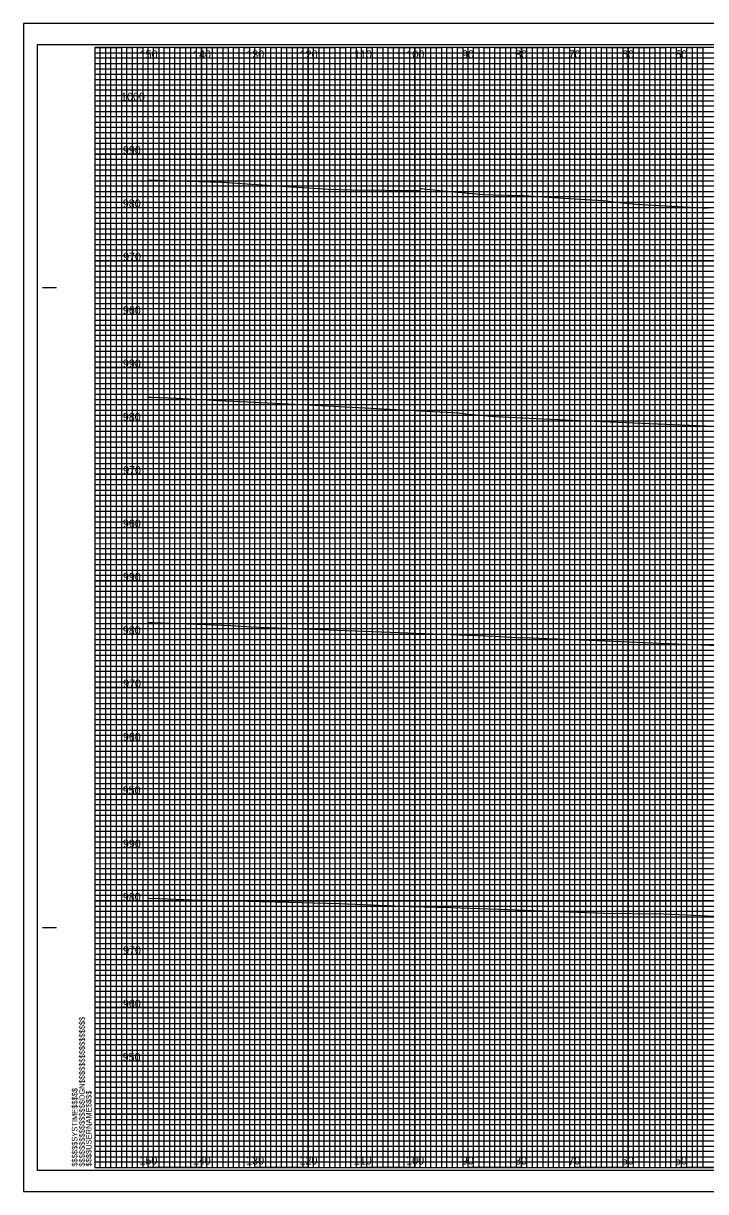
# Model space of a CAD drawing. Extents: x -13 to 760, y -5 to 1491.
# Drawn here: x 423.3 to 551.2, y 314.5 to 533.5 of the extents above; entities that cross this region are included whole.
import ezdxf

# ---------------------------------------------------------------- set-up
doc = ezdxf.new("R2010")
doc.units = 0
for name, color, linetype in [('Default', 7, 'Continuous'), ('Exist XS Ground Line', 7, 'Continuous'), ('Prop XS Elevation Labels', 7, 'Continuous'), ('Prop XS Offset Labels', 7, 'Continuous'), ('Sheet Cross Section CELL', 7, 'Continuous'), ('Sheet Cross Section Grid Major CELL', 7, 'Continuous'), ('Sheet Cross Section Grid Middle CELL', 7, 'Continuous'), ('Sheet Cross Section Grid Minor 1 CELL', 7, 'Continuous'), ('Sheet Cross Section Grid Minor 2 CELL', 7, 'Continuous'), ('Sheet Cutting Line CELL', 7, 'Continuous'), ('Sheet DOT Grid CELL', 7, 'Continuous'), ('Sheet Plot Border Inside CELL', 7, 'Continuous'), ('Sheet Plot Border Outside CELL', 7, 'Continuous')]:
    doc.layers.add(name, color=color, linetype=linetype)

msp = doc.modelspace()

# ---------------------------------------------------------------- linework, layer by layer
at = {"layer": 'Exist XS Ground Line'}
for points in [[(446.7, 504.16), (451.89, 503.99), (460.45, 503.71), (480.47, 502.43), (484.82, 502.27), (497.61, 502.17), (497.66, 502.17), (497.71, 502.17), (497.79, 502.5), (497.89, 502.52), (501.29, 502.2), (509.54, 501.41), (511.38, 501.37), (517.12, 501.21), (518.1, 501.15), (525.54, 500.68), (532.07, 500.32), (533.9, 500.06), (538.06, 499.6), (551.67, 498.85)], [(446.7, 504.16), (451.89, 503.99), (460.45, 503.71), (480.47, 502.43), (484.82, 502.27), (497.61, 502.17), (497.66, 502.17), (497.71, 502.17), (497.79, 502.5), (497.89, 502.52), (501.29, 502.2), (509.54, 501.41), (511.38, 501.37), (517.12, 501.21), (518.1, 501.15), (525.54, 500.68), (532.07, 500.32), (533.9, 500.06), (538.06, 499.6), (551.67, 498.85)], [(446.7, 463.45), (447.34, 463.43), (451.94, 463.25), (459.82, 462.83), (462.69, 462.7), (476.73, 462.02), (504.86, 460.48), (506.67, 460.24), (511.85, 459.84), (519.4, 459.42), (530.33, 458.91), (537.74, 458.61), (548.17, 458.18), (555.59, 457.89)], [(446.7, 463.45), (447.34, 463.43), (451.94, 463.25), (459.82, 462.83), (462.69, 462.7), (476.73, 462.02), (504.86, 460.48), (506.67, 460.24), (511.85, 459.84), (519.4, 459.42), (530.33, 458.91), (537.74, 458.61), (548.17, 458.18), (555.59, 457.89)], [(446.7, 421.25), (447.6, 421.19), (462.2, 420.6), (466.03, 420.41), (511.53, 418.63), (515.75, 418.41), (518.64, 418.29), (521.8, 418.19), (563.87, 416.45)], [(446.7, 421.25), (447.6, 421.19), (462.2, 420.6), (466.03, 420.41), (511.53, 418.63), (515.75, 418.41), (518.64, 418.29), (521.8, 418.19), (563.87, 416.45)], [(446.7, 369.54), (448.61, 369.45), (451.9, 369.31), (451.9, 369.31), (454.92, 369.22), (473.04, 368.78), (480.19, 368.56), (482.5, 368.49), (495.86, 367.98), (503.4, 367.74), (510.75, 367.51), (532.16, 366.7), (543.34, 366.61), (564.26, 365.65)], [(446.7, 369.54), (448.61, 369.45), (451.9, 369.31), (451.9, 369.31), (454.92, 369.22), (473.04, 368.78), (480.19, 368.56), (482.5, 368.49), (495.86, 367.98), (503.4, 367.74), (510.75, 367.51), (532.16, 366.7), (543.34, 366.61), (564.26, 365.65)]]:
    msp.add_lwpolyline(points, dxfattribs=at)
at = {"layer": 'Sheet Cross Section CELL'}
for p, q in [((426.9, 484), (429.4, 484)), ((427, 484), (429.5, 484)), ((426.9, 364), (429.4, 364)), ((427, 364), (429.5, 364)), ((436.7, 319), (436.7, 319)), ((436.7, 319), (436.7, 319)), ((436.7, 319), (436.7, 319)), ((436.7, 319), (436.7, 319)), ((436.7, 319), (436.7, 319)), ((436.7, 319), (436.7, 319)), ((436.7, 319), (436.7, 319))]:
    msp.add_line(p, q, dxfattribs=at)
msp.add_lwpolyline([(756.7, 529), (436.7, 529), (436.7, 319), (756.7, 319)], close=True, dxfattribs=at)
at = {"layer": 'Sheet Cross Section Grid Major CELL'}
for p, q in [((446.7, 529), (436.7, 529)), ((446.7, 319), (446.7, 529)), ((466.7, 529), (456.7, 529)), ((456.7, 529), (456.7, 319)), ((466.7, 319), (466.7, 529)), ((486.7, 529), (476.7, 529)), ((476.7, 529), (476.7, 319)), ((486.7, 319), (486.7, 529)), ((506.7, 529), (496.7, 529)), ((496.7, 529), (496.7, 319)), ((506.7, 319), (506.7, 529)), ((526.7, 529), (516.7, 529)), ((516.7, 529), (516.7, 319)), ((526.7, 319), (526.7, 529)), ((546.7, 529), (536.7, 529)), ((536.7, 529), (536.7, 319)), ((546.7, 319), (546.7, 529)), ((456.7, 319), (446.7, 319)), ((476.7, 319), (466.7, 319)), ((496.7, 319), (486.7, 319)), ((516.7, 319), (506.7, 319)), ((536.7, 319), (526.7, 319)), ((556.7, 319), (546.7, 319))]:
    msp.add_line(p, q, dxfattribs=at)
for points in [[(436.7, 519), (756.7, 519), (756.7, 509), (436.7, 509)], [(436.7, 499), (756.7, 499), (756.7, 489), (436.7, 489)], [(436.7, 479), (756.7, 479), (756.7, 469), (436.7, 469)], [(436.7, 459), (756.7, 459), (756.7, 449), (436.7, 449)], [(436.7, 439), (756.7, 439), (756.7, 429), (436.7, 429)], [(436.7, 419), (756.7, 419), (756.7, 409), (436.7, 409)], [(436.7, 399), (756.7, 399), (756.7, 389), (436.7, 389)], [(436.7, 379), (756.7, 379), (756.7, 369), (436.7, 369)], [(436.7, 359), (756.7, 359), (756.7, 349), (436.7, 349)], [(436.7, 339), (756.7, 339), (756.7, 329), (436.7, 329)]]:
    msp.add_lwpolyline(points, dxfattribs=at)
at = {"layer": 'Sheet Cross Section Grid Middle CELL'}
for points in [[(436.7, 529), (441.7, 529), (441.7, 319), (451.7, 319), (451.7, 529), (461.7, 529), (461.7, 319), (471.7, 319), (471.7, 529), (481.7, 529), (481.7, 319), (491.7, 319), (491.7, 529), (501.7, 529), (501.7, 319), (511.7, 319), (511.7, 529), (521.7, 529), (521.7, 319), (531.7, 319), (531.7, 529), (541.7, 529), (541.7, 319), (551.7, 319)], [(436.7, 524), (711.7, 524)], [(436.7, 504), (756.7, 504), (756.7, 514), (436.7, 514)], [(436.7, 484), (756.7, 484), (756.7, 494), (436.7, 494)], [(436.7, 464), (756.7, 464), (756.7, 474), (436.7, 474)], [(436.7, 444), (756.7, 444), (756.7, 454), (436.7, 454)], [(436.7, 424), (756.7, 424), (756.7, 434), (436.7, 434)], [(436.7, 404), (756.7, 404), (756.7, 414), (436.7, 414)], [(436.7, 384), (756.7, 384), (756.7, 394), (436.7, 394)], [(436.7, 364), (756.7, 364), (756.7, 374), (436.7, 374)], [(436.7, 344), (756.7, 344), (756.7, 354), (436.7, 354)], [(436.7, 324), (756.7, 324), (756.7, 334), (436.7, 334)]]:
    msp.add_lwpolyline(points, dxfattribs=at)
at = {"layer": 'Sheet Cross Section Grid Minor 1 CELL'}
for p, q in [((436.7, 528), (696.7, 528)), ((696.7, 526.98), (436.7, 526.98)), ((436.7, 526.98), (436.7, 526)), ((436.7, 526), (696.7, 526)), ((696.7, 524.89), (436.7, 524.89)), ((436.7, 524.89), (436.7, 523)), ((436.7, 523), (756.7, 523))]:
    msp.add_line(p, q, dxfattribs=at)
for points in [[(436.7, 522), (706.7, 522), (756.7, 522), (756.7, 521), (436.7, 521)], [(436.7, 520), (756.7, 520), (756.7, 518), (436.7, 518)], [(436.7, 517), (756.7, 517), (756.7, 516), (436.7, 515.98)], [(436.7, 515), (756.7, 515), (756.7, 513), (436.7, 513)], [(436.7, 512), (756.7, 512), (756.7, 511), (436.7, 511)], [(436.7, 510), (756.7, 510), (756.7, 508), (436.7, 508)], [(436.7, 507), (756.7, 507), (756.7, 506), (436.7, 506)], [(436.7, 505), (756.7, 505), (756.7, 503), (436.7, 503)], [(436.7, 502), (756.7, 502), (756.7, 501), (436.7, 501)], [(436.7, 500), (756.7, 500), (756.7, 498), (436.7, 498)], [(436.7, 497), (756.7, 497), (756.7, 496), (436.7, 496)], [(436.7, 495), (756.7, 495), (756.7, 492.95), (756.7, 492), (756.7, 491), (436.7, 491)], [(436.7, 493), (756.7, 493), (756.7, 492), (436.7, 492)], [(436.7, 490), (756.7, 490), (756.7, 488), (436.7, 488.03)], [(436.7, 488.03), (756.7, 488), (756.7, 487), (436.7, 487)], [(436.7, 486), (756.7, 486), (756.7, 485), (436.7, 485)], [(436.7, 483), (756.7, 483), (756.7, 482), (436.7, 482)], [(436.7, 481), (756.7, 481), (756.7, 480), (436.7, 480)], [(436.63, 477.89), (756.7, 477.89), (756.7, 476.88), (436.63, 476.88)], [(436.7, 476), (756.7, 476), (756.7, 475), (436.7, 475)], [(436.7, 473), (756.7, 473), (756.7, 472), (436.7, 472)], [(436.7, 471), (756.7, 471), (756.7, 470), (436.7, 470)], [(436.7, 468), (756.7, 468), (756.7, 467), (436.7, 467)], [(436.7, 466), (756.7, 466), (756.7, 465), (436.7, 465)], [(436.7, 463), (756.7, 463), (756.7, 462), (436.7, 462)], [(436.7, 461), (756.7, 461), (756.7, 460), (436.7, 460)], [(436.7, 458), (756.7, 458), (756.69, 456.98), (436.7, 457)], [(436.7, 456), (756.7, 456), (756.7, 455), (436.7, 455)], [(436.7, 453), (756.7, 453), (756.7, 452), (436.7, 452)], [(436.7, 451), (756.7, 451), (756.7, 450), (436.7, 450)], [(436.7, 448), (756.7, 448), (756.7, 447), (436.7, 447)], [(436.7, 446), (756.7, 446), (756.7, 445), (436.7, 445)], [(436.7, 443), (756.7, 443), (756.7, 442), (436.7, 442)], [(436.7, 441), (756.7, 441), (756.7, 440), (436.7, 440)], [(436.7, 438), (756.7, 438), (756.7, 437), (436.7, 437)], [(436.7, 435.99), (756.77, 435.91), (756.7, 435), (436.7, 435)], [(436.7, 433), (756.7, 433), (756.7, 432), (436.7, 432)], [(436.7, 431), (756.7, 431), (756.7, 430), (436.7, 430)], [(436.7, 428), (756.7, 428), (756.7, 427), (436.7, 427)], [(436.7, 426), (756.7, 426), (756.7, 425), (436.7, 425)], [(436.7, 423), (756.7, 423), (756.7, 422), (436.7, 422)], [(436.7, 421), (756.7, 421), (756.7, 420), (436.7, 420)], [(436.7, 418), (756.7, 418), (756.7, 417), (436.7, 417)], [(436.7, 416), (756.7, 416), (756.7, 415), (436.7, 415)], [(436.7, 413), (756.7, 413), (756.7, 412), (436.7, 412)], [(436.7, 411), (756.7, 411), (756.7, 410), (436.7, 410)], [(436.7, 408), (756.7, 408), (756.7, 407), (436.7, 407)], [(436.7, 406), (756.7, 406), (756.7, 405), (436.7, 405)], [(436.7, 403), (756.7, 403), (756.7, 402), (436.7, 402)], [(436.7, 401), (756.7, 401), (756.7, 400), (436.7, 400)], [(436.7, 398), (756.7, 398), (756.69, 396.98), (436.7, 397)], [(436.7, 396), (756.7, 396), (756.7, 395), (436.7, 395)], [(436.7, 393), (756.7, 393), (756.7, 392), (436.7, 392)], [(436.7, 391), (756.7, 391), (756.7, 390), (436.7, 390)], [(436.7, 388), (756.7, 388), (756.7, 387), (436.7, 387)], [(436.7, 386), (756.7, 386), (756.7, 385), (436.7, 385)], [(436.7, 383), (756.7, 383), (756.7, 382), (436.7, 382)], [(436.7, 381), (756.7, 381), (756.7, 380), (436.7, 380)], [(436.7, 378), (756.7, 378), (756.7, 377), (436.7, 377)], [(436.7, 375.99), (756.77, 375.91), (756.7, 375), (436.7, 375)], [(436.7, 373), (756.7, 373), (756.7, 372), (436.7, 372)], [(436.7, 371), (756.7, 371), (756.7, 370), (436.7, 370)], [(436.7, 368), (756.7, 368), (756.7, 367), (436.7, 367)], [(436.7, 366), (756.7, 366), (756.7, 365), (436.7, 365)], [(436.7, 363), (756.7, 363), (756.7, 362), (436.7, 362)], [(436.7, 361), (756.7, 361), (756.7, 360), (436.7, 360)], [(436.7, 358), (756.7, 358), (756.7, 357), (436.7, 357)], [(436.7, 356), (756.7, 356), (756.7, 355), (436.7, 355)], [(436.7, 353), (756.7, 353), (756.7, 352), (436.7, 352)], [(436.7, 351), (756.7, 351), (756.7, 350), (436.7, 350)], [(436.7, 348), (756.7, 348), (756.7, 347), (436.7, 347)], [(436.7, 346), (756.7, 346), (756.7, 345), (436.7, 345)], [(436.7, 343), (756.7, 343), (756.7, 342), (436.7, 342)], [(436.7, 341), (756.7, 341), (756.7, 340), (436.7, 340)], [(436.7, 338), (756.7, 338), (756.7, 337), (436.7, 337)], [(436.7, 336), (756.7, 336), (756.7, 335), (436.7, 335)], [(436.7, 333), (756.7, 333), (756.7, 332), (436.7, 332)], [(436.7, 331), (756.7, 331), (756.7, 330), (436.7, 330)], [(436.7, 328), (756.7, 328), (756.7, 327), (436.7, 327)], [(436.7, 326), (756.7, 326), (756.7, 325), (436.7, 325)], [(436.7, 323), (756.7, 323), (756.7, 322), (436.7, 322)], [(436.7, 321), (756.7, 321), (756.7, 320), (436.7, 320)]]:
    msp.add_lwpolyline(points, dxfattribs=at)
at = {"layer": 'Sheet Cross Section Grid Minor 2 CELL'}
for points in [[(436.7, 319), (437.7, 319), (437.7, 529), (438.7, 529), (438.7, 319)], [(438.7, 319), (439.7, 319), (439.7, 529), (440.7, 529), (440.7, 319)], [(441.7, 319), (442.7, 319), (442.7, 529), (443.7, 529), (443.7, 319)], [(443.7, 319), (444.7, 319), (444.7, 529), (445.7, 529), (445.7, 319)], [(446.7, 319), (447.7, 319), (447.7, 529), (448.7, 529), (448.7, 319)], [(448.7, 319), (449.7, 319), (449.7, 529), (450.7, 529), (450.7, 319)], [(451.7, 319), (452.7, 319), (452.7, 529), (453.7, 529), (453.7, 319)], [(453.7, 319), (454.7, 319), (454.7, 529), (455.7, 529), (455.7, 319)], [(456.7, 319), (457.7, 319), (457.7, 529), (458.7, 529), (458.7, 319)], [(458.7, 319), (459.7, 319), (459.7, 529), (460.7, 529), (460.7, 319)], [(461.7, 319), (462.7, 319), (462.7, 529), (463.7, 529), (463.7, 319)], [(463.7, 319), (464.7, 319), (464.7, 529), (465.7, 529), (465.7, 319)], [(466.7, 319), (467.7, 319), (467.7, 529), (468.7, 529), (468.7, 319)], [(468.7, 319), (469.7, 319), (469.7, 529), (470.7, 529), (470.7, 319)], [(471.7, 319), (472.7, 319), (472.7, 529), (473.7, 529), (473.7, 319)], [(473.7, 319), (474.7, 319), (474.7, 529), (475.7, 529), (475.7, 319)], [(476.7, 319), (477.7, 319), (477.7, 529), (478.7, 529), (478.7, 319)], [(478.7, 319), (479.7, 319), (479.7, 529), (480.7, 529), (480.7, 319)], [(481.7, 319), (482.7, 319), (482.7, 529), (483.7, 529), (483.7, 319)], [(483.7, 319), (484.7, 319), (484.7, 529), (485.7, 529), (485.7, 319)], [(486.7, 319), (487.7, 319), (487.7, 529), (488.7, 529), (488.7, 319)], [(488.7, 319), (489.7, 319), (489.7, 529), (490.7, 529), (490.7, 319)], [(491.7, 319), (492.7, 319), (492.7, 529), (493.7, 529), (493.7, 319)], [(493.7, 319), (494.7, 319), (494.7, 529), (495.7, 529), (495.7, 319)], [(496.7, 319), (497.7, 319), (497.7, 529), (498.7, 529), (498.7, 319)], [(498.7, 319), (499.7, 319), (499.7, 529), (500.7, 529), (500.7, 319)], [(501.7, 319), (502.7, 319), (502.7, 529), (503.7, 529), (503.7, 319)], [(503.7, 319), (504.7, 319), (504.7, 529), (505.7, 529), (505.7, 319)], [(506.7, 319), (507.7, 319), (507.7, 529), (508.7, 529), (508.7, 319)], [(508.7, 319), (509.7, 319), (509.7, 529), (510.7, 529), (510.7, 319)], [(511.7, 319), (512.7, 319), (512.7, 529), (513.7, 529), (513.7, 319)], [(513.7, 319), (514.7, 319), (514.7, 529), (515.7, 529), (515.7, 319)], [(516.7, 319), (517.7, 319), (517.7, 529), (518.7, 529), (518.7, 319)], [(518.7, 319), (519.7, 319), (519.7, 529), (520.7, 529), (520.7, 319)], [(521.7, 319), (522.7, 319), (522.7, 529), (523.7, 529), (523.7, 319)], [(523.7, 319), (524.7, 319), (524.7, 529), (525.7, 529), (525.7, 319)], [(526.7, 319), (527.7, 319), (527.7, 529), (528.7, 529), (528.7, 319)], [(528.7, 319), (529.7, 319), (529.7, 529), (530.7, 529), (530.7, 319)], [(531.7, 319), (532.7, 319), (532.7, 529), (533.7, 529), (533.7, 319)], [(533.7, 319), (534.7, 319), (534.7, 529), (535.7, 529), (535.7, 319)], [(536.7, 319), (537.7, 319), (537.7, 529), (538.7, 529), (538.7, 319)], [(538.7, 319), (539.7, 319), (539.7, 529), (540.7, 529), (540.7, 319)], [(541.7, 319), (542.7, 319), (542.7, 529), (543.7, 529), (543.7, 319)], [(543.7, 319), (544.7, 319), (544.7, 529), (545.7, 529), (545.7, 319)], [(546.7, 319), (547.7, 319), (547.7, 529), (548.7, 529), (548.7, 319)], [(548.7, 319), (549.7, 319), (549.7, 529), (550.7, 529), (550.7, 319)]]:
    msp.add_lwpolyline(points, dxfattribs=at)
at = {"layer": 'Sheet Cutting Line CELL'}
for p, q in [((760, 533.5), (423.3, 533.5)), ((423.3, 533.5), (423.3, 314.5)), ((423.3, 314.5), (760, 314.5))]:
    msp.add_line(p, q, dxfattribs=at)
at = {"layer": 'Sheet DOT Grid CELL'}
for p, q in [((446.7, 319), (446.7, 529)), ((456.7, 319), (456.7, 529)), ((466.7, 319), (466.7, 529)), ((476.7, 319), (476.7, 529)), ((486.7, 319), (486.7, 529)), ((496.7, 319), (496.7, 529)), ((506.7, 319), (506.7, 529)), ((516.7, 319), (516.7, 529)), ((526.7, 319), (526.7, 529)), ((536.7, 319), (536.7, 529)), ((546.7, 319), (546.7, 529)), ((436.7, 519), (756.7, 519)), ((436.7, 509), (756.7, 509)), ((436.7, 499), (756.7, 499)), ((436.7, 489), (756.7, 489)), ((436.7, 479), (756.7, 479)), ((436.7, 469), (756.7, 469)), ((436.7, 459), (756.7, 459)), ((436.7, 449), (756.7, 449)), ((436.7, 439), (756.7, 439)), ((436.7, 429), (756.7, 429)), ((436.7, 419), (756.7, 419)), ((436.7, 409), (756.7, 409)), ((436.7, 399), (756.7, 399)), ((436.7, 389), (756.7, 389)), ((436.7, 379), (756.7, 379)), ((436.7, 369), (756.7, 369)), ((436.7, 359), (756.7, 359)), ((436.7, 349), (756.7, 349)), ((436.7, 339), (756.7, 339)), ((436.7, 329), (756.7, 329))]:
    msp.add_line(p, q, dxfattribs=at)
at = {"layer": 'Sheet Plot Border Inside CELL'}
msp.add_lwpolyline([(425.9, 318.5), (759.1, 318.5), (759.1, 529.5), (425.9, 529.5)], close=True, dxfattribs=at)
at = {"layer": 'Sheet Plot Border Outside CELL'}
msp.add_lwpolyline([(423.3, 314.5), (760, 314.5), (760, 533.5), (423.3, 533.5)], close=True, dxfattribs=at)

# ---------------------------------------------------------------- texts
at = {"layer": 'Default'}
for p in [(446.7, 479), (446.7, 439), (446.7, 389), (446.7, 339)]:
    msp.add_text('-', height=0.0001, dxfattribs=at).set_placement(p)
at = {"layer": 'Prop XS Elevation Labels'}
for s, p in [('1000', (441.62, 519)), ('990', (441.96, 509)), ('980', (441.94, 499)), ('970', (442, 489)), ('960', (441.96, 479)), ('990', (441.96, 469)), ('980', (441.94, 459)), ('970', (442, 449)), ('960', (441.96, 439)), ('990', (441.96, 429)), ('980', (441.94, 419)), ('970', (442, 409)), ('960', (441.96, 399)), ('950', (441.92, 389)), ('990', (441.96, 379)), ('980', (441.94, 369)), ('970', (442, 359)), ('960', (441.96, 349)), ('950', (441.92, 339))]:
    msp.add_text(s, height=1.5, dxfattribs=at).set_placement(p)
at = {"layer": 'Prop XS Offset Labels'}
for s, p in [('150', (445.11, 526.94)), ('140', (455.11, 526.94)), ('130', (465.11, 526.94)), ('120', (475.11, 526.94)), ('110', (485.29, 526.94)), ('100', (495.11, 526.94)), ('90', (505.53, 526.94)), ('80', (515.53, 526.94)), ('70', (525.53, 526.94)), ('60', (535.53, 526.94)), ('50', (545.53, 526.94)), ('150', (445.07, 319.59)), ('140', (455.07, 319.59)), ('130', (465.07, 319.59)), ('120', (475.07, 319.59)), ('110', (485.25, 319.59)), ('100', (495.07, 319.59)), ('90', (505.48, 319.59)), ('80', (515.48, 319.59)), ('70', (525.48, 319.59)), ('60', (535.48, 319.59)), ('50', (545.48, 319.59))]:
    msp.add_text(s, height=1.5, dxfattribs=at).set_placement(p)
at = {"layer": 'Sheet Cross Section CELL'}
for s, p in [('$$$$$$$$$$$$$$$$DGN$$$$$$$$$$$$$$$$', (434.82, 319.18)), ('$$$$$$SYSTIME$$$$$', (433.44, 319.18)), ('$$$$USERNAME$$$$', (436.08, 319.23))]:
    msp.add_text(s, height=1.05, rotation=90, dxfattribs=at).set_placement(p)

doc.saveas('drawing.dxf')
